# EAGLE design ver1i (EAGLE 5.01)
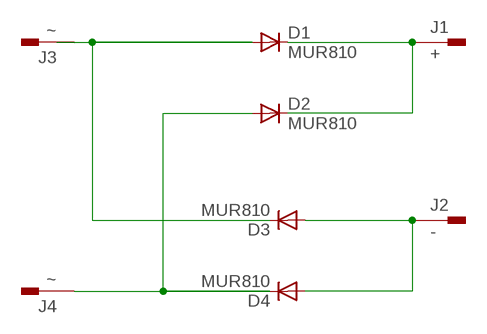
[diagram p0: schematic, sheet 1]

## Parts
D1  MUR810  [TO220ACS]
D2  MUR810  [TO220ACS]
D3  MUR810  [TO220ACS]
D4  MUR810  [TO220ACS]
J1  +  PIN2F061.200  [F061.200]
J2  -  PIN2F061.200  [F061.200]
J3  ~  PIN2F061.200  [F061.200]
J4  ~  PIN2F061.200  [F061.200]

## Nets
N$1: D1.C D2.C J1.1A
N$3: D1.A D3.C J3.1A J3.1B(1.1)
N$5: D3.A D4.A J2.1A
N$7: D2.A D4.C J4.1A
Unconnected: J1.1B(1.1) J2.1B(1.1) J4.1B(1.1)

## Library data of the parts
D1-D4 = diode:MUR810: DIODE
J1-J4 = con-faston:PIN2: Flachstecker Typ Tyco/Electronics/AMP TAB, FASTON

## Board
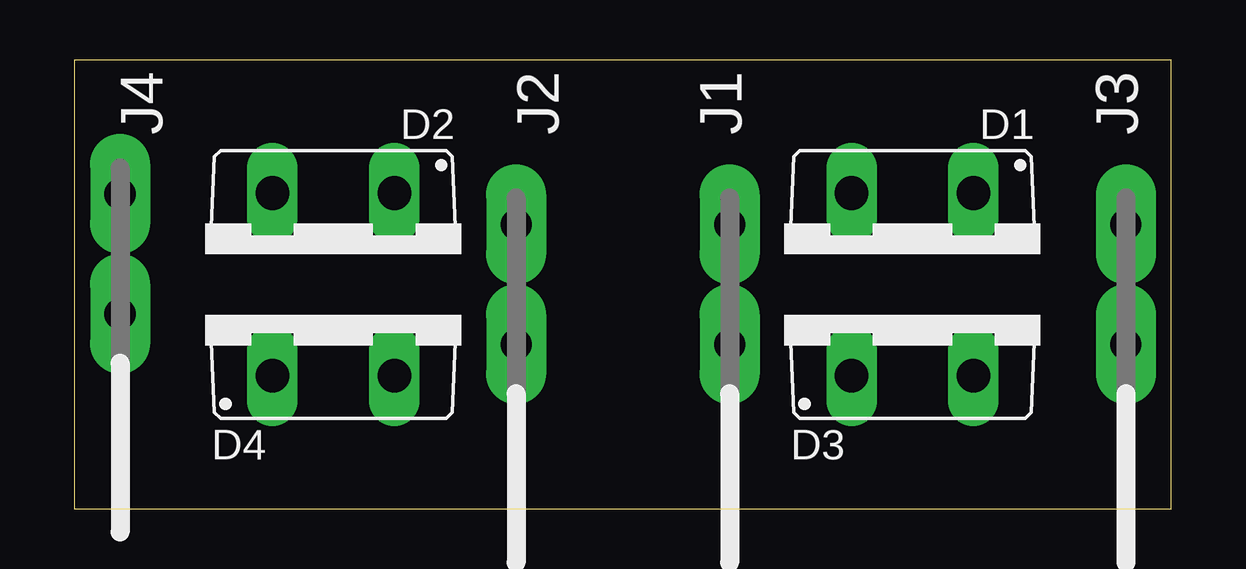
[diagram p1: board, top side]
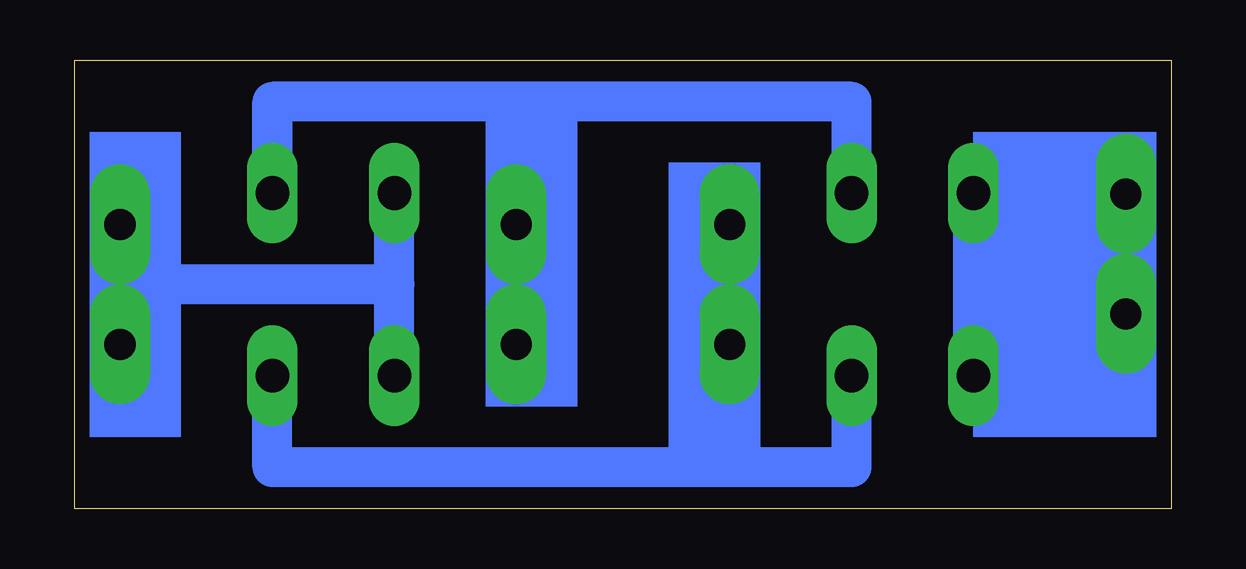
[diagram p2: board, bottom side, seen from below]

Size 45.7 x 18.72 mm. Coordinates in mm from the lower left corner, seen from the top.
Outline: 0,0 45.7,0 45.7,18.72 0,18.72 0,0
Copper layers (1*16): Top 0.035mm / dielectric 1.5mm / Bottom 0.035mm
Design rules "default": minimum track width 10mil, minimum drill 24mil, track to track 8mil, track to pad 8mil, pad to pad 8mil, via to via 8mil, smd to smd 8mil, copper to edge 40mil, drill to drill 8mil, minimum pad ring 10mil, minimum via ring 8mil, stop-mask expansion 4mil, vias tented up to drill 0mil, thermal gap 10mil

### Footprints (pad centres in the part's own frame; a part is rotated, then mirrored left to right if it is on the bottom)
TO220ACS = drill 1.4 long: A 2.54,-2.54; C -2.54,-2.54
F061.200 = drill 1.3 pad 2.5 long: 1A -2.5,0; 1B 2.5,0

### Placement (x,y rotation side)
D1  34.92,10.63 180 top
D2  10.79,10.63 180 top
D3  34.92,8.09 0 top
D4  10.79,8.09 0 top
J1  27.3,9.36 270 top
J2  18.41,9.36 270 top
J3  43.81,9.36 270 top
J4  1.9,10.63 270 top

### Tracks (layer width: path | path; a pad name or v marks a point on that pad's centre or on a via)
N$1
  Bottom 0.254: 13.33,16.98 D2.C 13.33,11.9
  Bottom 1.676: 13.33,16.98 27.3,16.98 | D1.C 37.46,16.98 27.3,16.98 | 27.3,16.98 J1.1A
N$2
  Bottom 1.676: 1.9,9.36 1.9,11.86
N$3
  Bottom 0.254: J3.1A 43.81,9.36 J3.1B
  Bottom 1.676: D3.C 32.38,9.36 | 32.38,9.36 D1.A | 32.38,9.36 43.81,9.36
N$4
  Bottom 1.676: 13.33,5.55 13.33,1.74 37.46,1.74 37.46,5.55
N$5
  Bottom 0.254: 18.41,1.74 13.33,1.74 D4.A | 18.41,1.74 37.46,1.74 D3.A 37.46,6.82 | 18.41,1.74 J2.1A
N$6
  Bottom 1.676: 37.46,14.44 37.46,16.98
N$7
  Bottom 0.254: 1.9,13.17 J4.1A
  Bottom 1.676: D4.C D2.A 1.9,13.17
N$8
  Bottom 1.676: 13.33,13.17 13.33,16.98
(copper drawn outside any net)
  shapes: Bottom area x5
